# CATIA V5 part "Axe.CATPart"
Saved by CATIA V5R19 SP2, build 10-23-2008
Part number: Axe
Bounding box of the stored display mesh (mm): x -6 to 6, y -22.75 to 54.75, z -6 to 6
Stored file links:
  F:\Projet CAO\pièces et assemblages\mécanisme 577\577-SaintAime\577-SaintAime\Axe.CATPart
  F:\Projet CAO\pièces et assemblages\mécanisme 577\577-SaintAime\577-SaintAime\mecanisme577_parametre.CATProduct
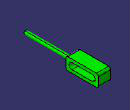
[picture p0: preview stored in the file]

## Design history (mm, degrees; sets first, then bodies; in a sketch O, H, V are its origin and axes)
Parameters
  Longueur_oblong = 20 mm {= External.diam_cyl + 14 mm}
External parameters (linked from other documents)
  External.diam_trou_de_passage = 4 mm
  External.diam_cyl = 6 mm
  External.ep_oreille = 6 mm
  External.entraxe = 25 mm
Body1 (main body)
  Sketch1 on yz-plane, origin (0, 0, 0), H (0, 1, 0), V (0, 0, 1)
    point P1 (-22.75, 0)
    line L1 (-22.75, 0) -> (-22.75, 2)
    line L2 (-22.75, 2) -> (20.75, 2)
    line L3 (20.75, 2) -> (20.75, 3)
    point P4 (20.75, 3)
    line L4 (20.75, 3) -> (22.75, 3.7279)
    line L5 (22.75, 3.7279) -> (22.75, 0)
    point P6 (22.75, 0)
    line L6 (22.75, 0) -> (-22.75, 0)
    angle L4 L5 = 70
    distance L2 L6 = 2 {= External.diam_trou_de_passage / 2}
    distance L3 L1 = 43.5 {= 2*(External.ep_oreille ) + External.entraxe + 6.5 mm}
    distance L3 L5 = 2
    distance P4 L6 = 3 {= External.diam_trou_de_passage / 2 + 1 mm}
    coincidence: P1 H, P6 H
    vertical: L1 V, L3 V, L5 V
    horizontal: L2 H, L6 H
    symmetry: L1 L5 V
  Shaft1: profile Sketch1, axis Sketch1.L6, angle 360
  Sketch2 on yz-plane, origin (0, 0, 0), H (0, 1, 0), V (0, 0, 1)
    arc A1 centre (24.75, 4) radius 2 from (22.75, 4) to (24.75, 6) cw
    line L1 (24.75, 6) -> (52.75, 6)
    arc A2 centre (52.75, 4) radius 2 from (52.75, 6) to (54.75, 4) cw
    line L2 (54.75, 4) -> (54.75, -4)
    arc A3 centre (52.75, -4) radius 2 from (54.75, -4) to (52.75, -6) cw
    line L3 (52.75, -6) -> (24.75, -6)
    arc A4 centre (24.75, -4) radius 2 from (24.75, -6) to (22.75, -4) cw
    line L4 (22.75, 4) -> (22.75, -4)
    construction line L5 (28.75, 0) -> (48.75, 0)
    point P13 (28.75, 0)
    point P14 (48.75, 0)
    line L6 (28.75, 3) -> (48.75, 3)
    line L7 (48.75, -3) -> (28.75, -3)
    arc A5 centre (48.75, 0) radius 3 from (48.75, 3) to (48.75, -3) cw
    arc A6 centre (28.75, 0) radius 3 from (28.75, -3) to (28.75, 3) cw
    construction line L8 (38.75, 17.8201) -> (38.75, -16.8608)
    reference intersected line E1 (22.75, 4.2279) -> (22.75, -4.2279) from face of Shaft1 from Sketch1.L5
    distance L5 L6 = 3 {= External.diam_cyl /2}
    radius A2 = 2
    radius A3 = 2
    radius A1 = 2
    radius A4 = 2
    distance P13 P14 = 20 {= Longueur_oblong}
    distance L8 L2 = 16 {= External.diam_cyl  + 10 mm}
    distance L5 L1 = 6 {= (External.diam_cyl /2) + 3 mm}
    tangency: L1 A1, A2 L1, A3 L2, L3 A3, A4 L3, A4 L4, L2 A2, L4 A1, A5 L6, A6 L6, A5 L7, A6 L7
    vertical: L4 V, L2 V, L8 V
    horizontal: L1 H, L5 H, L3 H
    coincidence: P13 H, L4 E1
    symmetry: P14 P13 L8, L4 L2 L8, L3 L1 L5
  Pad1: profile Sketch2, direction (1, 0, 0), length 6, mirrored extent
  Chamfer1: length 0.5, angle 45, on edge [face of Shaft1 from Sketch1.L1 | face of Shaft1 from Sketch1.L2]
